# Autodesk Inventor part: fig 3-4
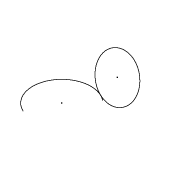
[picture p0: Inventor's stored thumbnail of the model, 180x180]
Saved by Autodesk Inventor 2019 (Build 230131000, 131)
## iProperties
Created: 2009-11
Part Number: fig 3-4
Document SubType Name: Modeling
Designer: Sham
Density: 1 g/cm^3
Material: Generic
Appearance: Default
Author: Sham
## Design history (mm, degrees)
sketch "Sketch1"
  geometry: A1 r 10.623 centre (-1.113, -21.203) between (5.463, -12.861) and (-5.537, -30.861); 1 further point; 1 other entity
  constraints: 2 point on circle, 1 centre point, 4 other
